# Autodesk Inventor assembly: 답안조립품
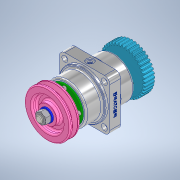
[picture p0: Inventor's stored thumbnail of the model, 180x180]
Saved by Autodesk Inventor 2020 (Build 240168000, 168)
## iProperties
Created: 2023-10
Part Number: 답안조립품
Document SubType Name: Assembly
Designer: oem
Author: oem
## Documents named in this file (12)
- C:\Users\oem\Desktop\731006V1002\답안조립품.iam
- C:\Users\oem\Desktop\731006V1002\본체.ipt
- C:\Users\oem\Desktop\731006V1002\베어링 6204.ipt
- C:\Users\oem\Desktop\731006V1002\축.ipt
- C:\Users\oem\Desktop\731006V1002\커버.ipt
- C:\Users\oem\Desktop\731006V1002\오일실 20x35x8.ipt
- C:\Users\oem\Desktop\731006V1002\볼트 M4x0.7.ipt
- C:\Users\oem\Desktop\731006V1002\키 5x5.ipt
- C:\Users\oem\Desktop\731006V1002\V벨트풀리.ipt
- C:\Users\oem\Desktop\731006V1002\스퍼기어.ipt
- C:\Users\oem\Desktop\731006V1002\와셔 12x24.ipt
- C:\Users\oem\Desktop\731006V1002\너트 M12x1.25.ipt
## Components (1 placed, 1 different names)
1. V벨트풀리:1 — 각도:5
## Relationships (1: Angle 1)
- 각도:5 [Angle]: V벨트풀리:1
